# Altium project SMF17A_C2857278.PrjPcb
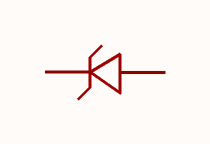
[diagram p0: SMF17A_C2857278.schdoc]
1 sheet, 1 parts. Net scope: global (net labels, ports and power ports of the same name join across sheets).

## Sheet SMF17A_C2857278.schdoc
size 127 x 101 mm

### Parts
D?  smf17a_c2857278  [SOD-123FL_L2.8-W1.8-LS3.6-RD]  (value not drawn)

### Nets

Not connected (* = marked no-connect by the designer): D? 1 2

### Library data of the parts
D? = smf17a_c2857278: 极性:单向;反向截止电压(Vrwm):17V;钳位电压:27.6V;峰值脉冲电流(Ipp):7.2A;峰值脉冲功率(Ppp):200W@10/1000us;击穿电压(VBR):18.9V;; Manufacturer: JSMSEMI(杰盛微); ManufacturerPart: SMF17A; AddInBom: yes; ModelId: 9a6bf0a398604d2998ad78800a7c8ef9; ModelTransform: 141.732,70.866,0,0,0,0,0,0,0; Polarity: 单向; Reverse Stand-Off Voltage (Vrwm): 17V; Clamping Voltage: 27.6V; Peak Pulse Current (Ipp): 7.2A; Voltage - Breakdown: 18.9V; Reverse Leakage Current (Ir): 1uA; Number of Channels: 单路; Type: TVS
